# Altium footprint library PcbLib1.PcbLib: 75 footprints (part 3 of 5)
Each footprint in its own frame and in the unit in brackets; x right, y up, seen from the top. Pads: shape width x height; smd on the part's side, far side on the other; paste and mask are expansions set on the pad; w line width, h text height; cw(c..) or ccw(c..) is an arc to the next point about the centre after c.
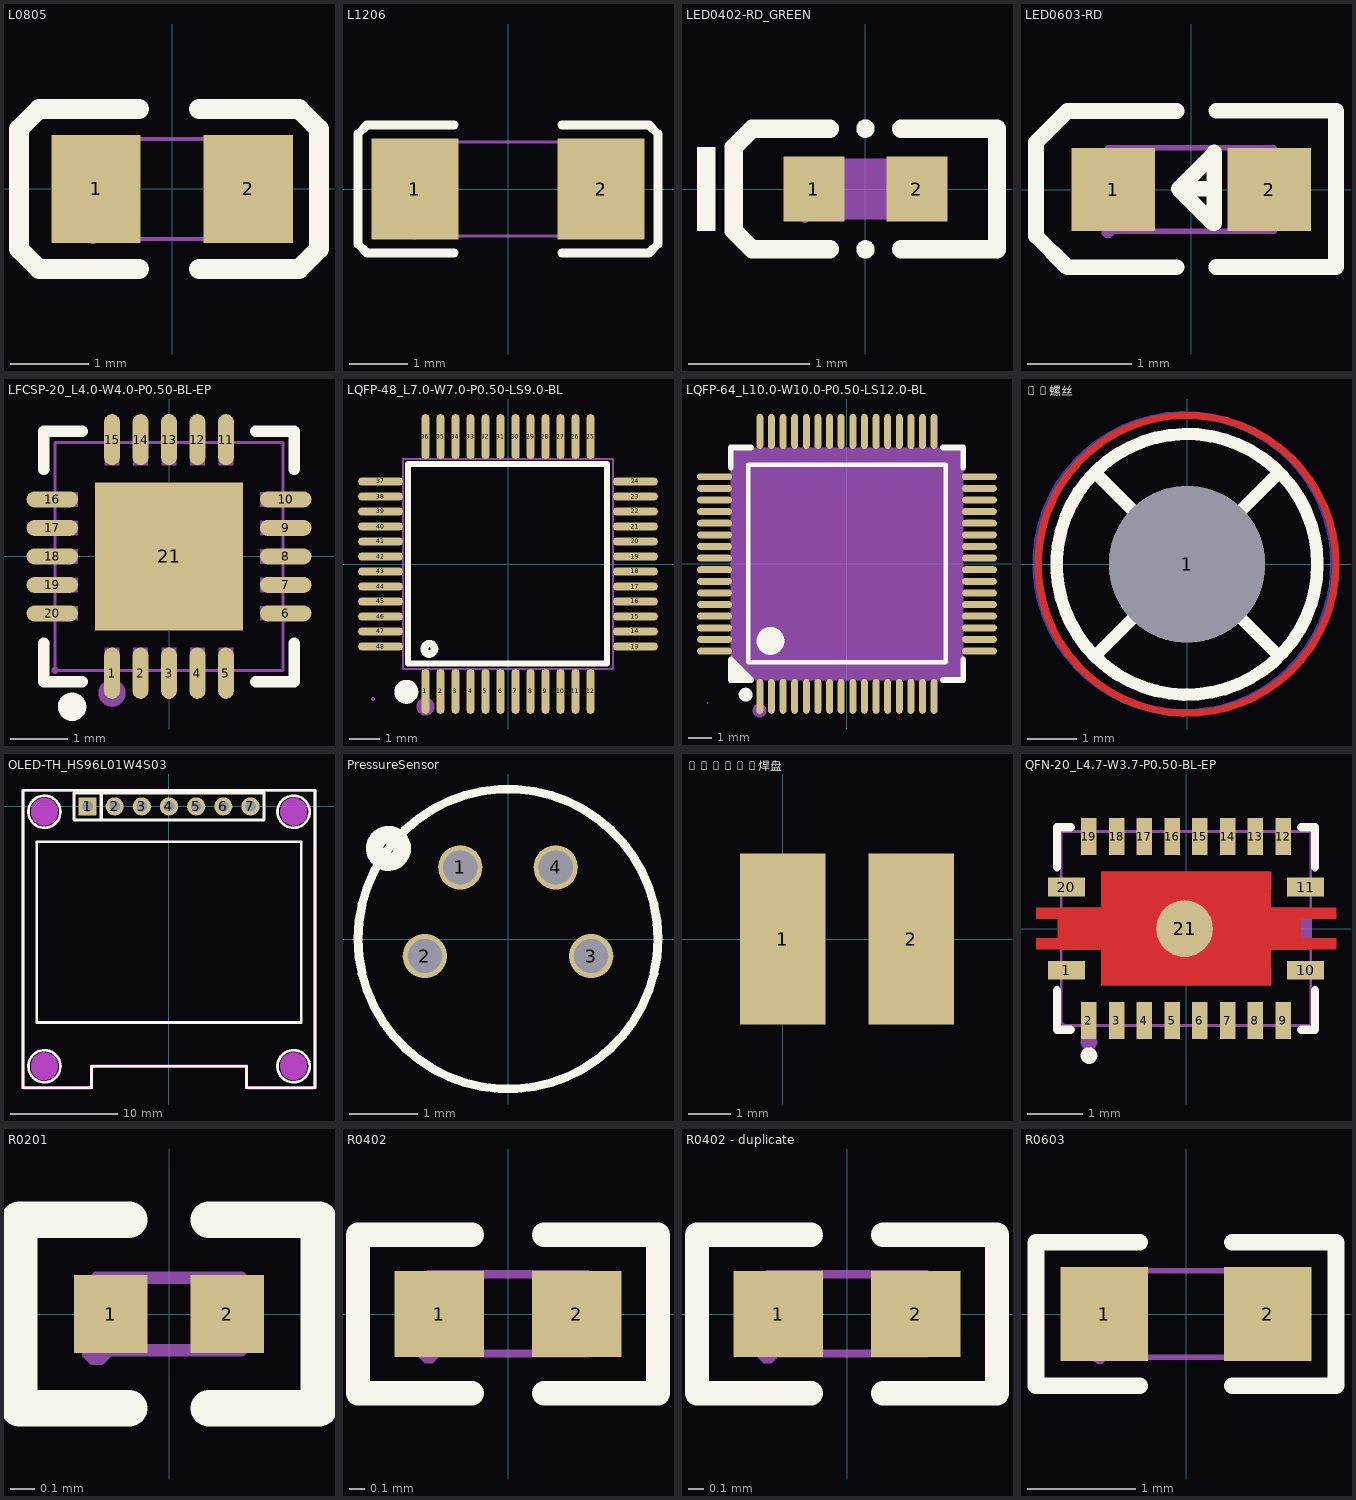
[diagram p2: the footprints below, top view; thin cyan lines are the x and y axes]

## L0805 [mm]
pads (2):
  rect 1.133x1.377 smd paste-100 mask+0.051: 1(-0.966,0) 2(0.966,0)
Top Overlay:
  lines w0.254: -0.421,-1.016 -1.691,-1.016 -1.945,-0.762 -1.945,-0.635 -1.945,0.762 -1.691,1.016 -1.564,1.016 -0.421,1.016 ; 0.341,-1.016 1.484,-1.016 1.611,-1.016 1.865,-0.762 1.865,0.635 1.865,0.762 1.611,1.016 0.341,1.016
Top Paste:
  region: 0.36,-0.22 0.36,0.22 0.745,0.689 1.433,0.689 1.533,0.589 1.533,-0.588 1.433,-0.688 0.745,-0.688
  region: -0.36,-0.22 -0.36,0.22 -0.745,0.689 -1.433,0.689 -1.533,0.589 -1.533,-0.588 -1.433,-0.688 -0.745,-0.688
Mechanical 6:
  lines w0.051: -1,-0.637 1,-0.637 1,0.638 -1,0.638 -1,-0.637
Mechanical 8:
  region: -0.94,-0.637 -0.94,-0.662 -0.975,-0.697 -1.025,-0.697 -1.06,-0.662 -1.06,-0.637 -1.06,-0.613 -1.025,-0.577 -0.975,-0.577 -0.94,-0.613 -0.94,-0.637
Mechanical 9:
  region: -1,-0.637 -1,0.638 -0.6,0.638 -0.6,-0.637
  region: 1,-0.637 1,0.638 0.6,0.638 0.6,-0.637

## L1206 [mm]
pads (2):
  rect 1.485x1.728 smd paste-100 mask+0.051: 1(-1.593,0) 2(1.593,0)
Top Overlay:
  lines w0.152: -0.926,-1.093 -2.411,-1.093 -2.564,-0.94 -2.564,0.94 -2.411,1.093 -0.926,1.093 ; 0.926,-1.093 2.411,-1.093 2.564,-0.94 2.564,0.94 2.411,1.093 0.926,1.093
Top Paste:
  region: -0.85,-0.764 -0.85,-0.394 -0.95,-0.294 -1.255,-0.294 -1.355,-0.194 -1.355,0.194 -1.255,0.294 -0.95,0.294 -0.85,0.394 -0.85,0.764 -0.95,0.864 -2.235,0.864 -2.335,0.764 -2.335,-0.764 -2.235,-0.864 -0.95,-0.864
  region: 0.85,-0.764 0.85,-0.394 0.95,-0.294 1.255,-0.294 1.355,-0.194 1.355,0.194 1.255,0.294 0.95,0.294 0.85,0.394 0.85,0.764 0.95,0.864 2.235,0.864 2.335,0.764 2.335,-0.764 2.235,-0.864 0.95,-0.864
Mechanical 6:
  lines w0.051: -1.6,-0.8 1.6,-0.8 1.6,0.8 -1.6,0.8 -1.6,-0.8
Mechanical 8:
  region: -1.54,-0.8 -1.54,-0.825 -1.575,-0.86 -1.625,-0.86 -1.66,-0.825 -1.66,-0.8 -1.66,-0.775 -1.625,-0.74 -1.575,-0.74 -1.54,-0.775 -1.54,-0.8
Mechanical 9:
  region: 1.6,-0.8 1.6,0.8 1.1,0.8 1.1,-0.8
  region: -1.6,-0.8 -1.6,0.8 -1.1,0.8 -1.1,-0.8

## LED0402-RD_GREEN [mm]
pads (2):
  rect 0.5x0.54 smd paste+0 mask+0.051: 1(-0.425,0) 2(0.425,0)
Top Overlay:
  circle w0.076: c0,0.499 r0.038
  circle w0.076: c0,-0.499 r0.038
  region: -1.237,-0.346 -1.237,0.346 -1.39,0.346 -1.39,-0.346
  lines w0.152: -0.296,-0.499 -0.933,-0.499 -1.085,-0.346 -1.085,0.346 -0.933,0.499 -0.296,0.499 ; 0.296,-0.499 1.085,-0.499 1.085,0.499 0.296,0.499
Mechanical 5:
  region: 0.35,-0.2 0.35,0.2 0.29,0.2 0.29,-0.2
  region: 0.44,-0.03 0.44,0.03 0.2,0.03 0.2,-0.03
  region: -0.44,-0.03 -0.44,0.03 -0.2,0.03 -0.2,-0.03
Mechanical 9:
  region: -0.5,-0.25 -0.5,0.25 0.5,0.25 0.5,-0.25
Mechanical 11:
  region: -0.47,-0.25 -0.47,-0.262 -0.487,-0.28 -0.512,-0.28 -0.53,-0.262 -0.53,-0.25 -0.53,-0.238 -0.512,-0.22 -0.487,-0.22 -0.47,-0.238 -0.47,-0.25
Mechanical 12:
  region: 0.5,-0.25 0.5,0.25 0.3,0.25 0.3,-0.25
  region: -0.5,-0.25 -0.5,0.25 -0.3,0.25 -0.3,-0.25

## LED0603-RD [mm]
pads (2):
  rect 0.8x0.8 smd: 1(-0.749,0) 2(0.749,0)
Top Overlay:
  lines w0.15: -0.14,-0.746 -1.19,-0.746 -1.49,-0.446 -1.49,-0.346 -1.49,0.354 -1.49,0.454 -1.19,0.754 -0.14,0.754 ; 0.22,0.007 -0.12,0.007 ; 0.24,-0.744 1.39,-0.744 ; 0.24,0.757 1.39,0.757 1.39,-0.723 ; -0.12,0.007 0.21,-0.324 0.22,-0.324 0.22,0.357 0.22,0.347 -0.12,0.007
Mechanical 2:
  region: -1.07,0.062 -0.53,0.062 -0.53,-0.068 -1.07,-0.068
  region: 0.735,-0.267 0.735,0.273 0.865,0.273 0.865,-0.267
  region: 0.529,0.068 1.069,0.068 1.069,-0.062 0.529,-0.062
Mechanical 6:
  lines w0.051: -0.8,-0.4 -0.8,0.4 0.8,0.4 0.8,-0.4 -0.8,-0.4
Mechanical 8:
  region: -0.739,-0.403 -0.739,-0.428 -0.775,-0.463 -0.824,-0.463 -0.859,-0.428 -0.859,-0.403 -0.859,-0.379 -0.824,-0.344 -0.775,-0.344 -0.739,-0.379 -0.739,-0.403
Mechanical 9:
  region: -0.8,-0.403 -0.8,0.397 -0.5,0.397 -0.5,-0.403
  region: 0.5,-0.396 0.5,0.404 0.8,0.404 0.8,-0.396

## LFCSP-20_L4.0-W4.0-P0.50-BL-EP [mm]
pads (21):
  oval 0.28x0.9 smd paste-100 mask+0.051: 1(-1,-2.05) 2(-0.5,-2.05) 3(0,-2.05) 4(0.5,-2.05) 5(1,-2.05) 11(1,2.05) 12(0.5,2.05) 13(0,2.05) 14(-0.5,2.05) 15(-1,2.05)
  oval 0.9x0.28 smd paste-100 mask+0.051: 6(2.05,-1) 7(2.05,-0.5) 8(2.05,0) 9(2.05,0.5) 10(2.05,1) 16(-2.05,1) 17(-2.05,0.5) 18(-2.05,0) 19(-2.05,-0.5) 20(-2.05,-1)
  rect 2.6x2.6 smd paste-100 mask+0.051: 21(0,0)
Top Overlay:
  lines w0.2: -2.2,-1.525 -2.2,-2.2 -1.525,-2.2 ; -2.2,1.525 -2.2,2.2 -1.525,2.2 ; 1.525,-2.2 2.2,-2.2 2.2,-1.525 ; 1.525,2.2 2.2,2.2 2.2,1.525
  lines w0.25: -1.703,-2.517 ccw(c-1.702,-2.642) -1.701,-2.517
Top Paste:
  drawing of 21 lines, arcs and shapes, not listed
Mechanical 2:
  circle w0.24: c-1,-2.4 r0.12
Mechanical 6:
  lines w0.051: -2,-2 -2,2 2,2 2,-2 -2,-2
Mechanical 8:
  region: -1.94,-2 -1.94,-2.025 -1.975,-2.06 -2.025,-2.06 -2.06,-2.025 -2.06,-2 -2.06,-1.975 -2.025,-1.94 -1.975,-1.94 -1.94,-1.975 -1.94,-2
Mechanical 9:
  region: -1.125,-2 -1.125,-1.6 -0.875,-1.6 -0.875,-2
  region: -0.625,-2 -0.625,-1.6 -0.375,-1.6 -0.375,-2
  region: -0.125,-2 -0.125,-1.6 0.125,-1.6 0.125,-2
  region: 0.375,-2 0.375,-1.6 0.625,-1.6 0.625,-2
  region: 0.875,-2 0.875,-1.6 1.125,-1.6 1.125,-2
  region: 1.6,-1.125 1.6,-0.875 2,-0.875 2,-1.125
  region: 1.6,-0.625 1.6,-0.375 2,-0.375 2,-0.625
  region: 1.6,-0.125 1.6,0.125 2,0.125 2,-0.125
  region: 1.6,0.375 1.6,0.625 2,0.625 2,0.375
  region: 1.6,0.875 1.6,1.125 2,1.125 2,0.875
  region: 0.875,1.6 0.875,2 1.125,2 1.125,1.6
  region: 0.375,1.6 0.375,2 0.625,2 0.625,1.6
  region: -0.125,1.6 -0.125,2 0.125,2 0.125,1.6
  region: -0.625,1.6 -0.625,2 -0.375,2 -0.375,1.6
  region: -1.125,1.6 -1.125,2 -0.875,2 -0.875,1.6
  region: -2,0.875 -2,1.125 -1.6,1.125 -1.6,0.875
  region: -2,0.375 -2,0.625 -1.6,0.625 -1.6,0.375
  region: -2,-0.125 -2,0.125 -1.6,0.125 -1.6,-0.125
  region: -2,-0.625 -2,-0.375 -1.6,-0.375 -1.6,-0.625
  region: -2,-1.125 -2,-0.875 -1.6,-0.875 -1.6,-1.125
  region: -1.25,-1.25 -1.25,1.25 1.25,1.25 1.25,-1.25

## LQFP-48_L7.0-W7.0-P0.50-LS9.0-BL [mm]
pads (48):
  oval 0.27x1.5 smd paste+0 mask+0.05: 1(-2.75,-4.25) 2(-2.25,-4.25) 3(-1.75,-4.25) 4(-1.25,-4.25) 5(-0.75,-4.25) 6(-0.25,-4.25) 7(0.25,-4.25) 8(0.75,-4.25) 9(1.25,-4.25) 10(1.75,-4.25) 11(2.25,-4.25) 12(2.75,-4.25) 25(2.75,4.25) 26(2.25,4.25) 27(1.75,4.25) 28(1.25,4.25) 29(0.75,4.25) 30(0.25,4.25) 31(-0.25,4.25) 32(-0.75,4.25) 33(-1.25,4.25) 34(-1.75,4.25) 35(-2.25,4.25) 36(-2.75,4.25)
  oval 1.5x0.27 smd paste+0 mask+0.05: 13(4.25,-2.75) 14(4.25,-2.25) 15(4.25,-1.75) 16(4.25,-1.25) 17(4.25,-0.75) 18(4.25,-0.25) 19(4.25,0.25) 20(4.25,0.75) 21(4.25,1.25) 22(4.25,1.75) 23(4.25,2.25) 24(4.25,2.75) 37(-4.25,2.75) 38(-4.25,2.25) 39(-4.25,1.75) 40(-4.25,1.25) 41(-4.25,0.75) 42(-4.25,0.25) 43(-4.25,-0.25) 44(-4.25,-0.75) 45(-4.25,-1.25) 46(-4.25,-1.75) 47(-4.25,-2.25) 48(-4.25,-2.75)
Top Overlay:
  circle w0.254: c-2.62,-2.83 r0.17
  lines w0.2: -2.896,3.34 3.302,3.34 3.302,-3.315 -3.327,-3.315 -3.327,3.34 -2.565,3.34
  lines w0.4: -3.39,-4.06 ccw(c-3.389,-4.26) -3.387,-4.06
Mechanical 2:
  circle w0.3: c-2.75,-4.75 r0.15
Mechanical 6:
  lines w0.051: -3.5,-3.5 3.5,-3.5 3.5,3.5 -3.5,3.5 -3.5,-3.5
Mechanical 7:
  drawing of 48 lines, arcs and shapes, not listed
Mechanical 8:
  region: -4.44,-4.5 -4.44,-4.525 -4.475,-4.56 -4.525,-4.56 -4.56,-4.525 -4.56,-4.5 -4.56,-4.475 -4.525,-4.44 -4.475,-4.44 -4.44,-4.475 -4.44,-4.5
Mechanical 9:
  drawing of 48 lines, arcs and shapes, not listed

## LQFP-64_L10.0-W10.0-P0.50-LS12.0-BL [mm]
pads (64):
  oval 0.3x1.5 smd paste+0 mask+0.051: 1(-3.75,-5.7) 2(-3.25,-5.7) 3(-2.75,-5.7) 4(-2.25,-5.7) 5(-1.75,-5.7) 6(-1.25,-5.7) 7(-0.75,-5.7) 8(-0.25,-5.7) 9(0.25,-5.7) 10(0.75,-5.7) 11(1.25,-5.7) 12(1.75,-5.7) 13(2.25,-5.7) 14(2.75,-5.7) 15(3.25,-5.7) 16(3.75,-5.7) 33(3.75,5.7) 34(3.25,5.7) 35(2.75,5.7) 36(2.25,5.7) 37(1.75,5.7) 38(1.25,5.7) 39(0.75,5.7) 40(0.25,5.7) 41(-0.25,5.7) 42(-0.75,5.7) 43(-1.25,5.7) 44(-1.75,5.7) 45(-2.25,5.7) 46(-2.75,5.7) 47(-3.25,5.7) 48(-3.75,5.7)
  oval 1.5x0.3 smd paste+0 mask+0.051: 17(5.7,-3.75) 18(5.7,-3.25) 19(5.7,-2.75) 20(5.7,-2.25) 21(5.7,-1.75) 22(5.7,-1.25) 23(5.7,-0.75) 24(5.7,-0.25) 25(5.7,0.25) 26(5.7,0.75) 27(5.7,1.25) 28(5.7,1.75) 29(5.7,2.25) 30(5.7,2.75) 31(5.7,3.25) 32(5.7,3.75) 49(-5.7,3.75) 50(-5.7,3.25) 51(-5.7,2.75) 52(-5.7,2.25) 53(-5.7,1.75) 54(-5.7,1.25) 55(-5.7,0.75) 56(-5.7,0.25) 57(-5.7,-0.25) 58(-5.7,-0.75) 59(-5.7,-1.25) 60(-5.7,-1.75) 61(-5.7,-2.25) 62(-5.7,-2.75) 63(-5.7,-3.25) 64(-5.7,-3.75)
Top Overlay:
  region: -4.131,-4.988 -5,-4.119 -5,-4.988
  lines w0.2: -4.25,-4.238 -4.25,4.262 4.25,4.262 4.25,-4.238 -4.25,-4.238
  lines w0.254: -5,4.143 -5,5.012 -4.131,5.012 ; 4.131,-4.988 5,-4.988 5,-4.119 ; 4.131,5.012 5,5.012 5,4.143 ; -5,-4.119 -5,-4.119 ; -5,-4.119 -4.131,-4.988 -5,-4.988 -5,-4.119
  lines w0.3: -4.361,-5.478 ccw(c-4.36,-5.628) -4.359,-5.478
  lines w0.6: -3.299,-3.013 ccw(c-3.297,-3.313) -3.294,-3.013
Mechanical 5:
  circle w0.3: c-3.76,-6.308 r0.15
Mechanical 9:
  region: -5,5 5,5 5,-5 -5,-5
Mechanical 10:
  drawing of 64 lines, arcs and shapes, not listed
Mechanical 11:
  region: -5.97,-5.988 -5.97,-6.001 -5.988,-6.018 -6.012,-6.018 -6.03,-6.001 -6.03,-5.988 -6.03,-5.976 -6.012,-5.958 -5.988,-5.958 -5.97,-5.976 -5.97,-5.988
Mechanical 12:
  drawing of 64 lines, arcs and shapes, not listed

## M3螺丝 [mil]
pads (1):
  round 126 hole 126 paste-99999 mask+4: 1(0,0)
Top Layer:
  circle w6: c0,0 r120
Bottom Layer:
  circle w6: c-1.69,0.46 r120
Top Overlay:
  circle w10: c0,0 r105
  lines w10: -72.5,-72.5 72.5,72.5 ; -72.5,72.5 72.5,-72.5

## OLED-TH_HS96L01W4S03 [mm]
pads (7):
  rect 1.7x1.7 hole 1: 1(-7.62,0)
  round 1.7 hole 1: 2(-5.08,0) 3(-2.54,0) 4(0,0) 5(2.54,0) 6(5.08,0) 7(7.62,0)
Top Overlay:
  circle w0.254: c-11.65,-0.5 r1.5
  circle w0.254: c11.65,-0.5 r1.5
  circle w0.254: c11.65,-24.3 r1.5
  circle w0.254: c-11.65,-24.3 r1.5
  lines w0.254: -13.65,-26.3 -13.65,1.5 13.65,1.5 13.65,-26.3 7.25,-26.3 7.25,-24.3 -7.25,-24.3 -7.25,-26.3 -13.65,-26.3 ; -12.37,-20.2 -12.37,-3.3 12.37,-3.3 12.37,-20.2 -12.37,-20.2
  lines w0.31: -6.35,-1.27 -6.35,1.27 ; 8.89,1.27 -8.89,1.27 -8.89,-1.27 8.89,-1.27 8.89,1.29
Keep-Out Layer:
  board cut-out: 12.9,-24.3 12.9,-24.464 12.815,-24.782 12.65,-25.067 12.417,-25.3 12.132,-25.465 11.815,-25.55 11.485,-25.55 11.167,-25.465 10.882,-25.3 10.65,-25.067 10.485,-24.782 10.4,-24.464 10.4,-24.3 10.4,-24.135 10.485,-23.817 10.65,-23.532 10.882,-23.3 11.167,-23.135 11.485,-23.05 11.815,-23.05 12.132,-23.135 12.417,-23.3 12.65,-23.532 12.815,-23.817 12.9,-24.135 12.9,-24.3
  board cut-out: -10.4,-24.3 -10.4,-24.464 -10.485,-24.782 -10.65,-25.067 -10.882,-25.3 -11.167,-25.465 -11.485,-25.55 -11.815,-25.55 -12.132,-25.465 -12.417,-25.3 -12.65,-25.067 -12.815,-24.782 -12.9,-24.464 -12.9,-24.3 -12.9,-24.135 -12.815,-23.817 -12.65,-23.532 -12.417,-23.3 -12.132,-23.135 -11.815,-23.05 -11.485,-23.05 -11.167,-23.135 -10.882,-23.3 -10.65,-23.532 -10.485,-23.817 -10.4,-24.135 -10.4,-24.3
  board cut-out: -10.4,-0.5 -10.4,-0.664 -10.485,-0.982 -10.65,-1.267 -10.882,-1.5 -11.167,-1.665 -11.485,-1.75 -11.815,-1.75 -12.132,-1.665 -12.417,-1.5 -12.65,-1.267 -12.815,-0.982 -12.9,-0.664 -12.9,-0.5 -12.9,-0.335 -12.815,-0.017 -12.65,0.268 -12.417,0.5 -12.132,0.665 -11.815,0.75 -11.485,0.75 -11.167,0.665 -10.882,0.5 -10.65,0.268 -10.485,-0.017 -10.4,-0.335 -10.4,-0.5
  board cut-out: 12.9,-0.5 12.9,-0.664 12.815,-0.982 12.65,-1.267 12.417,-1.5 12.132,-1.665 11.815,-1.75 11.485,-1.75 11.167,-1.665 10.882,-1.5 10.65,-1.267 10.485,-0.982 10.4,-0.664 10.4,-0.5 10.4,-0.335 10.485,-0.017 10.65,0.268 10.882,0.5 11.167,0.665 11.485,0.75 11.815,0.75 12.132,0.665 12.417,0.5 12.65,0.268 12.815,-0.017 12.9,-0.335 12.9,-0.5
Keep-Out Layer:
  drawing of 12 lines, arcs and shapes, not listed
Mechanical 1:
  circle w0.003: c11.65,-24.3 r1.25
  circle w0.003: c-11.65,-24.3 r1.25
  circle w0.003: c-11.65,-0.5 r1.25
  circle w0.003: c11.65,-0.5 r1.25
Mechanical 2:
  circle w1.25: c-11.65,-24.3 r0.625
  circle w1.25: c11.65,-24.3 r0.625
  circle w1.25: c11.65,-0.5 r0.625
  circle w1.25: c-11.65,-0.5 r0.625
  region: 13.65,1.373 -13.65,1.373 -13.699,1.383 -13.74,1.41 -13.767,1.451 -13.777,1.5 -13.767,1.549 -13.74,1.59 -13.699,1.617 -13.65,1.627 13.65,1.627 13.699,1.617 13.74,1.59 13.767,1.549 13.777,1.5 13.767,1.451 13.74,1.41 13.699,1.383
  region: -13.523,1.5 -13.523,-26.173 -7.377,-26.173 -7.377,-24.3 -7.367,-24.251 -7.34,-24.21 -7.299,-24.183 -7.25,-24.173 7.25,-24.173 7.299,-24.183 7.34,-24.21 7.367,-24.251 7.377,-24.3 7.377,-26.173 13.523,-26.173 13.523,1.5 13.533,1.549 13.56,1.59 13.601,1.617 13.65,1.627 13.699,1.617 13.74,1.59 13.767,1.549 13.777,1.5 13.777,-26.3 13.767,-26.349 13.74,-26.39 13.699,-26.417 13.65,-26.427 7.25,-26.427 7.201,-26.417 7.16,-26.39 7.133,-26.349 7.123,-26.3 7.123,-24.427 -7.123,-24.427 -7.123,-26.3 -7.133,-26.349 -7.16,-26.39 -7.201,-26.417 -7.25,-26.427 -13.65,-26.427 -13.699,-26.417 -13.74,-26.39 -13.767,-26.349 -13.777,-26.3 -13.777,1.5 -13.767,1.549 -13.74,1.59 -13.699,1.617 -13.65,1.627 -13.601,1.617 -13.56,1.59 -13.533,1.549
Mechanical 6:
  lines w0.051: -13.65,-26.3 -7.25,-26.3 -7.25,-24.3 7.25,-24.3 7.25,-26.3 13.65,-26.3 13.65,1.5 -13.65,1.5 -13.65,-26.3
Mechanical 8:
  region: -13.59,-26.3 -13.59,-26.325 -13.625,-26.36 -13.675,-26.36 -13.71,-26.325 -13.71,-26.3 -13.71,-26.275 -13.675,-26.24 -13.625,-26.24 -13.59,-26.275 -13.59,-26.3
Mechanical 9:
  region: 7.3,0.32 7.94,0.32 7.94,-0.32 7.3,-0.32
  region: 4.76,0.32 5.4,0.32 5.4,-0.32 4.76,-0.32
  region: 2.22,0.32 2.86,0.32 2.86,-0.32 2.22,-0.32
  region: -0.32,0.32 0.32,0.32 0.32,-0.32 -0.32,-0.32
  region: -2.86,0.32 -2.22,0.32 -2.22,-0.32 -2.86,-0.32
  region: -5.4,0.32 -4.76,0.32 -4.76,-0.32 -5.4,-0.32
  region: -7.94,0.32 -7.3,0.32 -7.3,-0.32 -7.94,-0.32

## PressureSensor [mm]
pads (4):
  round 0.65 / inner round 1.15 / far side round 1.15 hole 0.5: 1(-0.7,1.05) 2(-1.22,-0.25) 3(1.22,-0.25) 4(0.7,1.05)
Top Overlay:
  circle w0.127: c0,0 r2.2
  circle w0.254: c-1.753,1.329 r0.203

## PT1000焊盘 [mm]
pads (2):
  rect 2x4 smd: 1(0,0) 2(3,0)

## QFN-20_L4.7-W3.7-P0.50-BL-EP [mm]
pads (21):
  rect 0.665x0.336 smd: 1(-2.157,-0.75) 10(2.157,-0.75) 11(2.157,0.75) 20(-2.157,0.75)
  rect 0.28x0.665 smd: 2(-1.75,-1.657) 3(-1.25,-1.657) 4(-0.75,-1.657) 5(-0.25,-1.657) 6(0.25,-1.657) 7(0.75,-1.657) 8(1.25,-1.657) 9(1.75,-1.657) 12(1.75,1.658) 13(1.25,1.658) 14(0.75,1.658) 15(0.25,1.658) 16(-0.25,1.658) 17(-0.75,1.658) 18(-1.25,1.658) 19(-1.75,1.658)
  round 1.025 smd: 21(-0.026,0)
Top Layer:
  region: -2.705,0.38 -2.705,0.175 -2.315,0.175 -2.315,-0.175 -2.705,-0.175 -2.705,-0.375 -1.525,-0.375 -1.525,-1.025 1.525,-1.025 1.525,-0.375 2.705,-0.375 2.705,-0.175 2.065,-0.175 2.065,0.175 2.705,0.175 2.705,0.375 1.525,0.375 1.525,1.025 -1.525,1.025 -1.525,0.375
Top Overlay:
  circle w0.15: c-1.75,-2.29 r0.075
  lines w0.152: -2.326,-1.109 -2.326,-1.826 -2.08,-1.826 ; -2.326,1.109 -2.326,1.826 -2.08,1.826 ; 2.08,-1.826 2.326,-1.826 2.326,-1.109 ; 2.08,1.826 2.326,1.826 2.326,1.109
Mechanical 2:
  circle w0.15: c-1.75,-2.05 r0.075
Mechanical 6:
  lines w0.051: -2.25,-1.75 2.25,-1.75 2.25,1.75 -2.25,1.75 -2.25,-1.75
Mechanical 8:
  region: -2.19,-1.75 -2.19,-1.775 -2.225,-1.81 -2.275,-1.81 -2.31,-1.775 -2.31,-1.75 -2.31,-1.725 -2.275,-1.69 -2.225,-1.69 -2.19,-1.725 -2.19,-1.75
Mechanical 9:
  region: -1.87,-1.75 -1.87,-1.35 -1.63,-1.35 -1.63,-1.75
  region: -1.37,-1.75 -1.37,-1.35 -1.13,-1.35 -1.13,-1.75
  region: -0.87,-1.75 -0.87,-1.35 -0.63,-1.35 -0.63,-1.75
  region: -0.37,-1.75 -0.37,-1.35 -0.13,-1.35 -0.13,-1.75
  region: 0.13,-1.75 0.13,-1.35 0.37,-1.35 0.37,-1.75
  region: 0.63,-1.75 0.63,-1.35 0.87,-1.35 0.87,-1.75
  region: 1.13,-1.75 1.13,-1.35 1.37,-1.35 1.37,-1.75
  region: 1.63,-1.75 1.63,-1.35 1.87,-1.35 1.87,-1.75
  region: 1.85,-0.87 1.85,-0.63 2.25,-0.63 2.25,-0.87
  region: 1.85,0.63 1.85,0.87 2.25,0.87 2.25,0.63
  region: 1.63,1.75 1.63,1.35 1.87,1.35 1.87,1.75
  region: 1.13,1.75 1.13,1.35 1.37,1.35 1.37,1.75
  region: 0.63,1.75 0.63,1.35 0.87,1.35 0.87,1.75
  region: 0.13,1.75 0.13,1.35 0.37,1.35 0.37,1.75
  region: -0.37,1.75 -0.37,1.35 -0.13,1.35 -0.13,1.75
  region: -0.87,1.75 -0.87,1.35 -0.63,1.35 -0.63,1.75
  region: -1.37,1.75 -1.37,1.35 -1.13,1.35 -1.13,1.75
  region: -1.87,1.75 -1.87,1.35 -1.63,1.35 -1.63,1.75
  region: -1.85,0.63 -1.85,0.87 -2.25,0.87 -2.25,0.63
  region: -1.85,-0.87 -1.85,-0.63 -2.25,-0.63 -2.25,-0.87
  region: -1.528,-0.38 -2.25,-0.38 -2.25,0.38 -1.517,0.38 -1.512,1.025 1.537,1.025 1.53,0.38 2.25,0.38 2.25,-0.38 1.53,-0.38 1.537,-1.025 -1.53,-1.03

## R0201 [mm]
pads (2):
  rect 0.303x0.324 smd paste-100 mask+0.051: 1(-0.242,0) 2(0.242,0)
Top Overlay:
  lines w0.152: -0.166,-0.391 -0.622,-0.391 -0.622,0.391 -0.166,0.391 ; 0.166,-0.391 0.622,-0.391 0.622,0.391 0.166,0.391
Top Paste:
  region: -0.081,-0.138 -0.081,0.138 -0.105,0.162 -0.369,0.162 -0.393,0.138 -0.393,-0.138 -0.369,-0.162 -0.105,-0.162
  region: 0.081,-0.138 0.081,0.138 0.105,0.162 0.369,0.162 0.393,0.138 0.393,-0.138 0.369,-0.162 0.105,-0.162
Mechanical 6:
  lines w0.051: -0.3,-0.15 0.3,-0.15 0.3,0.15 -0.3,0.15 -0.3,-0.15
Mechanical 8:
  region: -0.24,-0.15 -0.24,-0.175 -0.275,-0.21 -0.325,-0.21 -0.36,-0.175 -0.36,-0.15 -0.36,-0.125 -0.325,-0.09 -0.275,-0.09 -0.24,-0.125 -0.24,-0.15
Mechanical 9:
  region: 0.3,-0.15 0.3,0.15 0.15,0.15 0.15,-0.15
  region: -0.3,-0.15 -0.3,0.15 -0.15,0.15 -0.15,-0.15

## R0402 [mm]
pads (2):
  rect 0.566x0.54 smd paste-100 mask+0.051: 1(-0.433,0) 2(0.433,0)
Top Overlay:
  lines w0.152: -0.226,-0.499 -0.944,-0.499 -0.944,0.499 -0.226,0.499 ; 0.226,-0.499 0.944,-0.499 0.944,0.499 0.226,0.499
Top Paste:
  region: 0.135,-0.23 0.135,0.23 0.175,0.27 0.676,0.27 0.716,0.23 0.716,-0.23 0.676,-0.27 0.175,-0.27
  region: -0.135,-0.23 -0.135,0.23 -0.175,0.27 -0.676,0.27 -0.716,0.23 -0.716,-0.23 -0.676,-0.27 -0.175,-0.27
Mechanical 6:
  lines w0.051: -0.5,-0.25 -0.5,0.25 0.5,0.25 0.5,-0.25 -0.5,-0.25
Mechanical 8:
  region: -0.44,-0.25 -0.44,-0.275 -0.475,-0.31 -0.525,-0.31 -0.56,-0.275 -0.56,-0.25 -0.56,-0.225 -0.525,-0.19 -0.475,-0.19 -0.44,-0.225 -0.44,-0.25
Mechanical 9:
  region: 0.251,-0.25 0.251,0.25 0.501,0.25 0.501,-0.25
  region: -0.249,0.25 -0.249,-0.25 -0.499,-0.25 -0.499,0.25

## R0402 - duplicate [mm]
pads (2):
  rect 0.566x0.54 smd paste-100 mask+0.051: 1(-0.433,0) 2(0.433,0)
Top Overlay:
  lines w0.152: -0.226,-0.499 -0.944,-0.499 -0.944,0.499 -0.226,0.499 ; 0.226,-0.499 0.944,-0.499 0.944,0.499 0.226,0.499
Top Paste:
  region: -0.135,-0.23 -0.135,0.23 -0.175,0.27 -0.676,0.27 -0.716,0.23 -0.716,-0.23 -0.676,-0.27 -0.175,-0.27
  region: 0.135,-0.23 0.135,0.23 0.175,0.27 0.676,0.27 0.716,0.23 0.716,-0.23 0.676,-0.27 0.175,-0.27
Mechanical 6:
  lines w0.051: -0.5,-0.25 0.5,-0.25 0.5,0.25 -0.5,0.25 -0.5,-0.25
Mechanical 8:
  region: -0.44,-0.25 -0.44,-0.275 -0.475,-0.31 -0.525,-0.31 -0.56,-0.275 -0.56,-0.25 -0.56,-0.225 -0.525,-0.19 -0.475,-0.19 -0.44,-0.225 -0.44,-0.25
Mechanical 9:
  region: -0.249,0.25 -0.249,-0.25 -0.499,-0.25 -0.499,0.25
  region: 0.251,-0.25 0.251,0.25 0.501,0.25 0.501,-0.25

## R0603 [mm]
pads (2):
  rect 0.806x0.864 smd paste-100 mask+0.051: 1(-0.753,0) 2(0.753,0)
Top Overlay:
  lines w0.152: -0.426,-0.661 -1.385,-0.661 -1.385,0.661 -0.426,0.661 ; 0.426,-0.661 1.385,-0.661 1.385,0.661 0.426,0.661
Top Paste:
  region: -1.195,-0.45 -0.395,-0.45 -0.345,-0.4 -0.345,-0.172 -0.715,-0.172 -0.715,0.158 -0.345,0.158 -0.345,0.4 -0.395,0.45 -1.195,0.45 -1.245,0.4 -1.245,-0.4
  region: 1.195,0.45 0.395,0.45 0.345,0.4 0.345,0.172 0.715,0.172 0.715,-0.158 0.345,-0.158 0.345,-0.4 0.395,-0.45 1.195,-0.45 1.245,-0.4 1.245,0.4
Mechanical 6:
  lines w0.051: -0.8,-0.4 0.8,-0.4 0.8,0.4 -0.8,0.4 -0.8,-0.4
Mechanical 8:
  region: -0.74,-0.4 -0.74,-0.425 -0.775,-0.46 -0.825,-0.46 -0.86,-0.425 -0.86,-0.4 -0.86,-0.375 -0.825,-0.34 -0.775,-0.34 -0.74,-0.375 -0.74,-0.4
Mechanical 9:
  region: 0.8,-0.4 0.8,0.4 0.5,0.4 0.5,-0.4
  region: -0.8,-0.4 -0.8,0.4 -0.5,0.4 -0.5,-0.4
